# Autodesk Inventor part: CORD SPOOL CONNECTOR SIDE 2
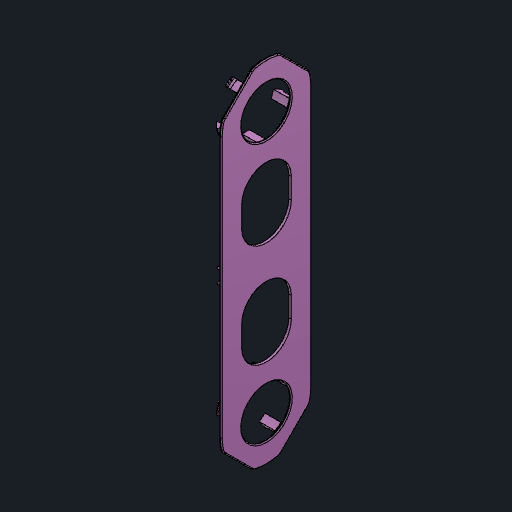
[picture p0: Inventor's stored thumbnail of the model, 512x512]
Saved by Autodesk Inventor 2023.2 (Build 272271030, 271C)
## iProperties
Created: 2022-11
Part Number: CORD SPOOL CONNECTOR SIDE 2
Material: Generic
Document SubType Name: Modeling
Designer: AR
Mass: 27.3079 g
Surface Area: 292.101 cm^2
Volume: 27.3079 cm^3
Density: 1 g/cm^3
Appearance: Smooth - Purple
Author: AR
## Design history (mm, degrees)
derived "_2 SPOOL CORD WRAP MP.ipt"
feature "PRUSA CORD SPOOL CONNECTOR SIDE 2::_2 SPOOL CORD WRAP MP.ipt" dims "d0" = 10
tag "TaggingFeature1"
node "PRUSA CORD SPOOL CONNECTOR SIDE 2"
